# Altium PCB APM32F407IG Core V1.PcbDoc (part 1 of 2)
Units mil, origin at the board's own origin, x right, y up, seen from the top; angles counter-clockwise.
Board outline 2360 x 2950 mil, 4 copper layers (Top Layer, Signal, GND, Bottom Layer); 55 components, 152 nets, 502 pads, 608 vias.
Unrouted connection lines stored in the file: 294.
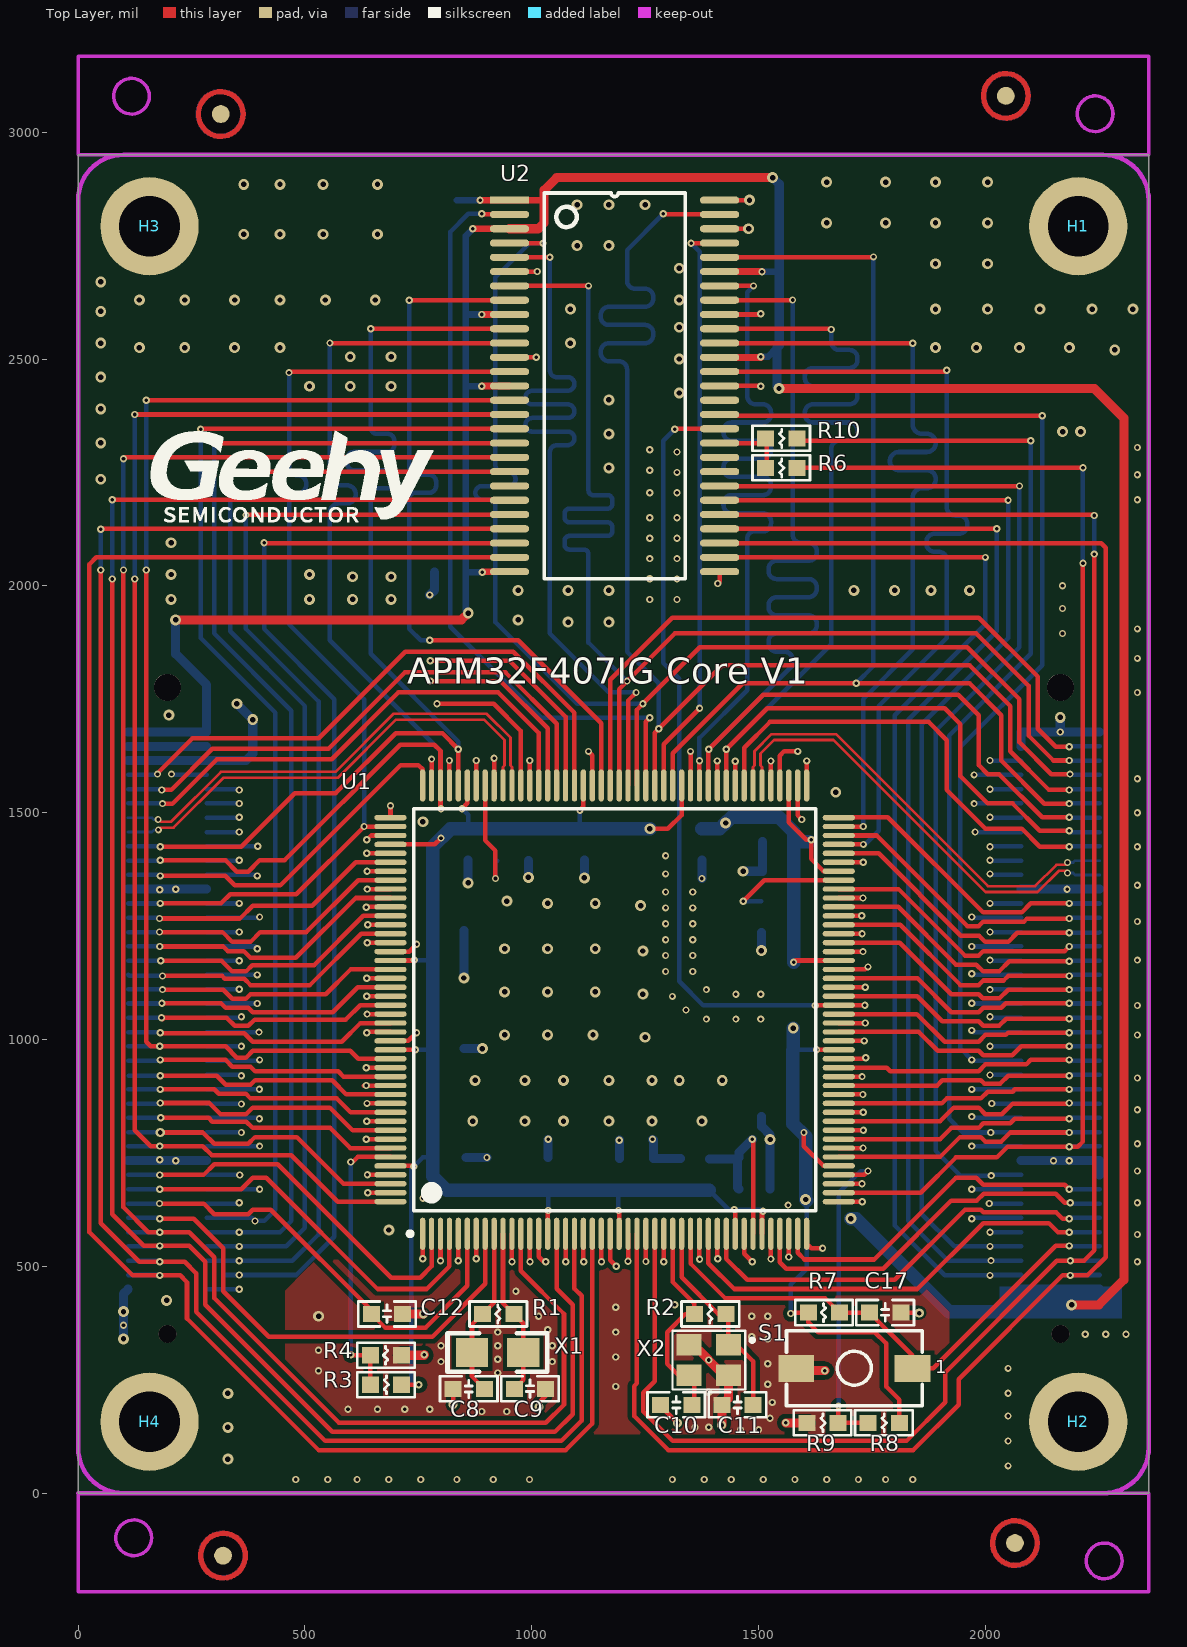
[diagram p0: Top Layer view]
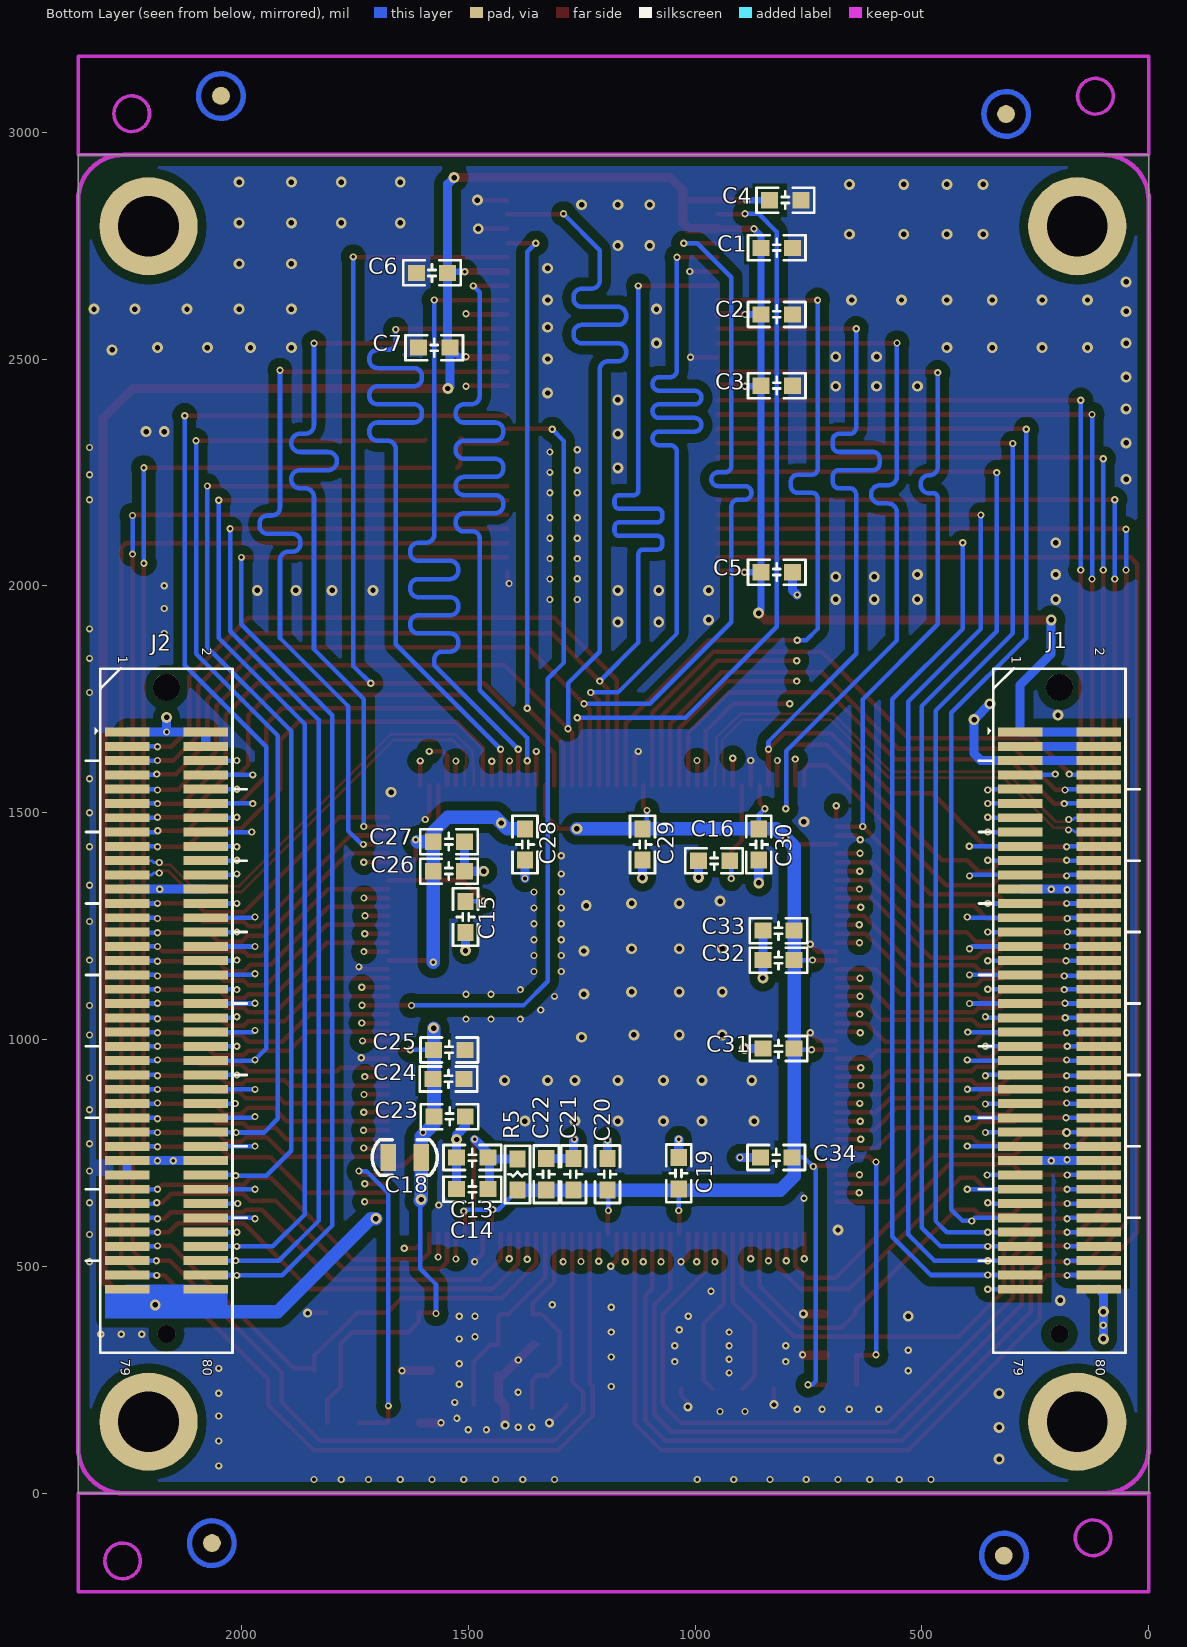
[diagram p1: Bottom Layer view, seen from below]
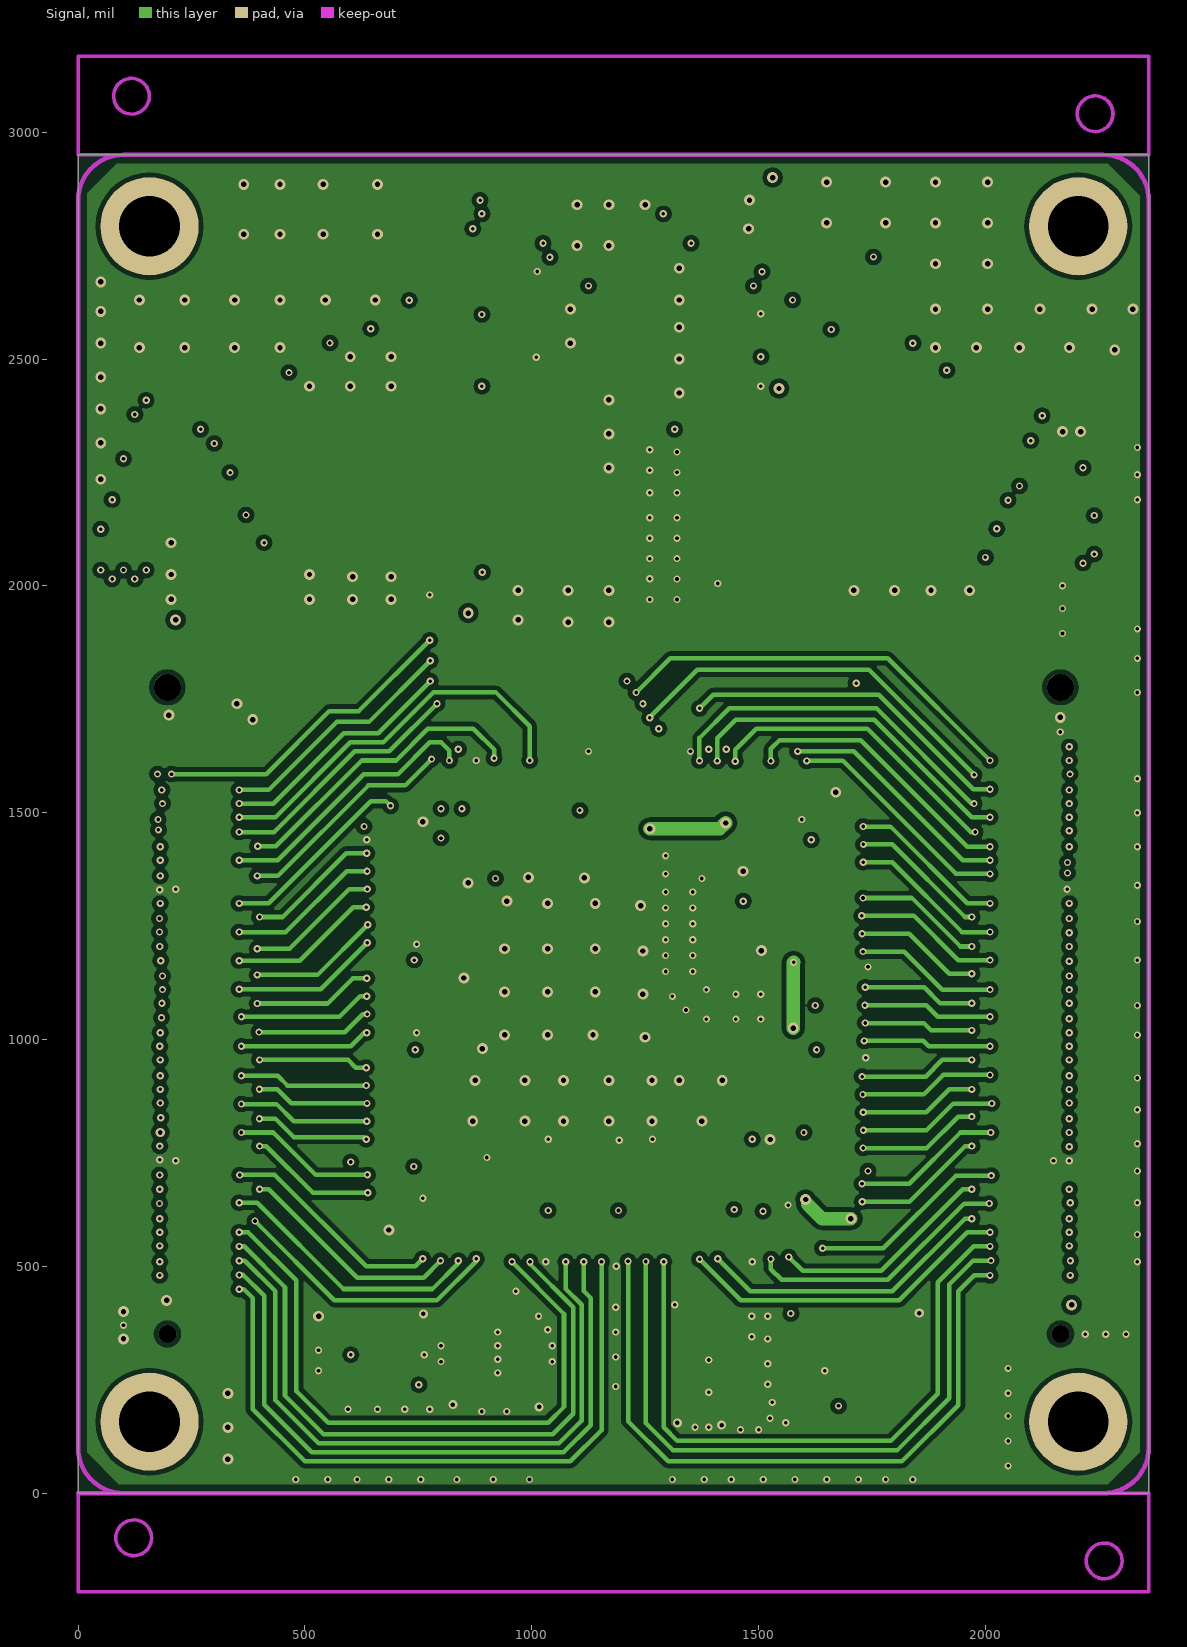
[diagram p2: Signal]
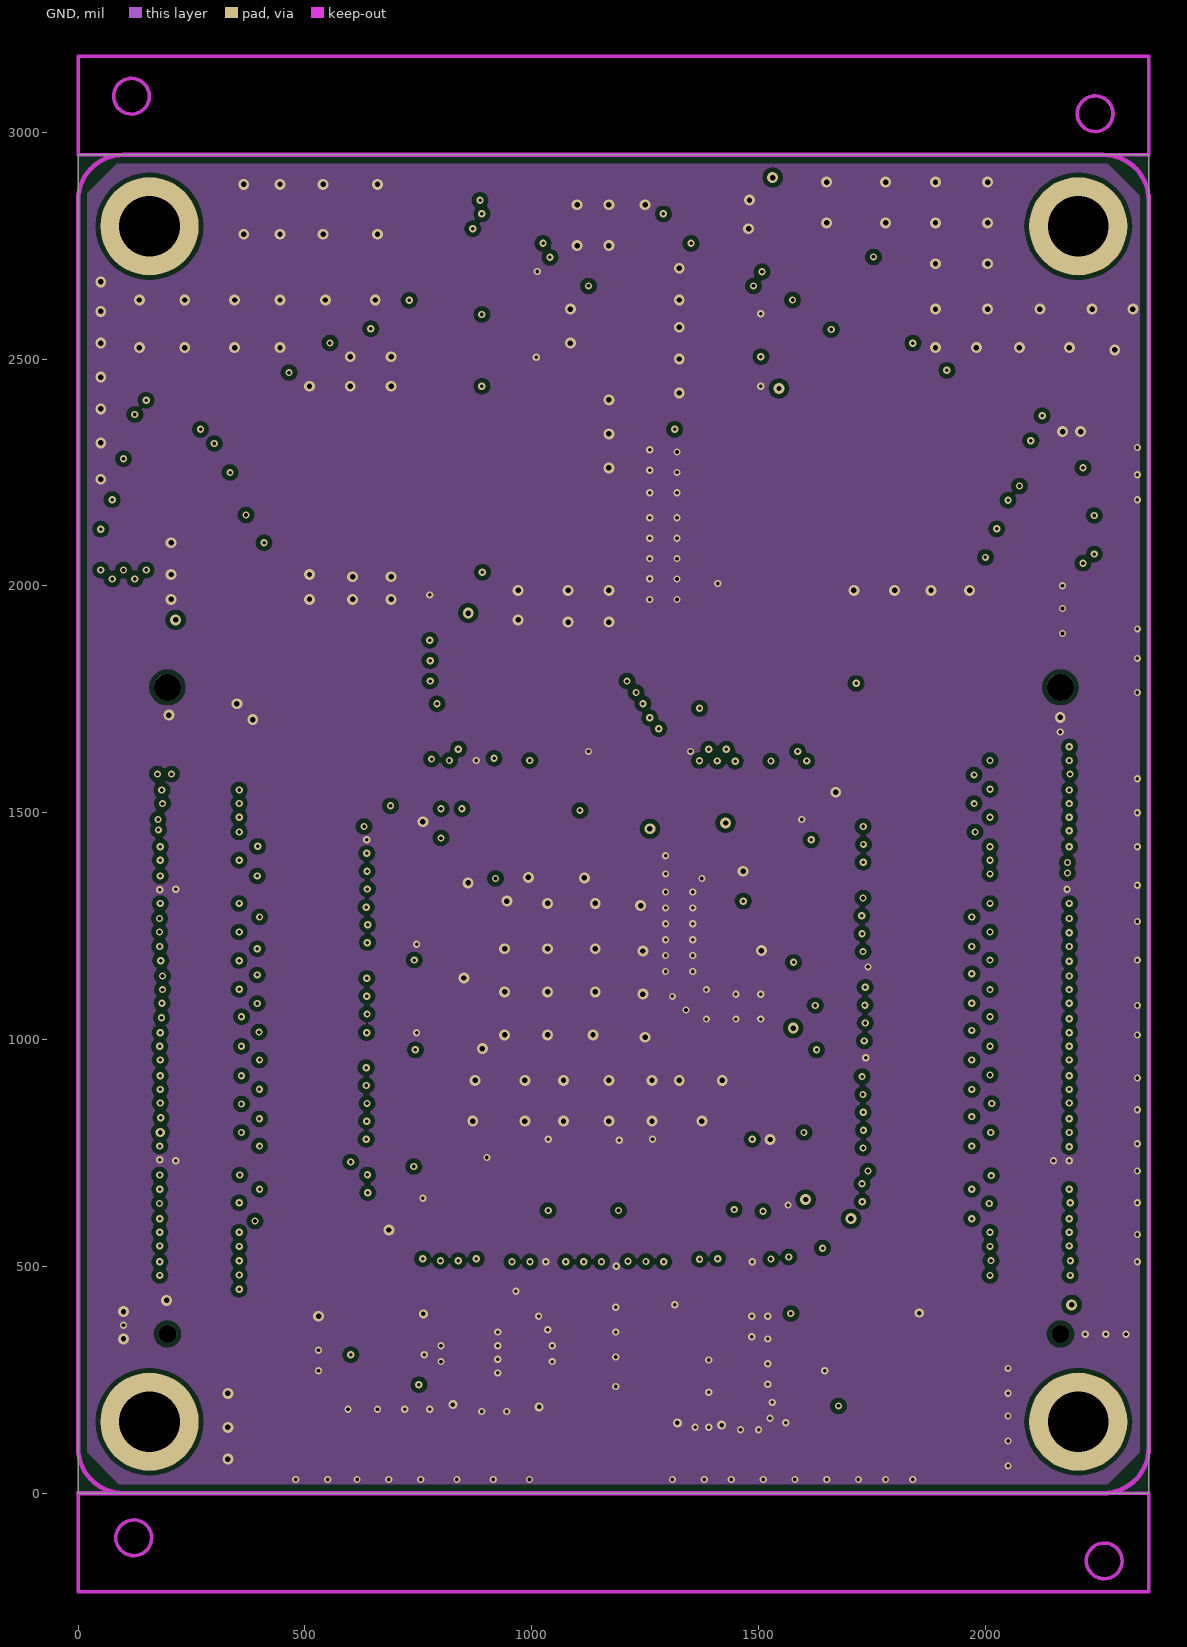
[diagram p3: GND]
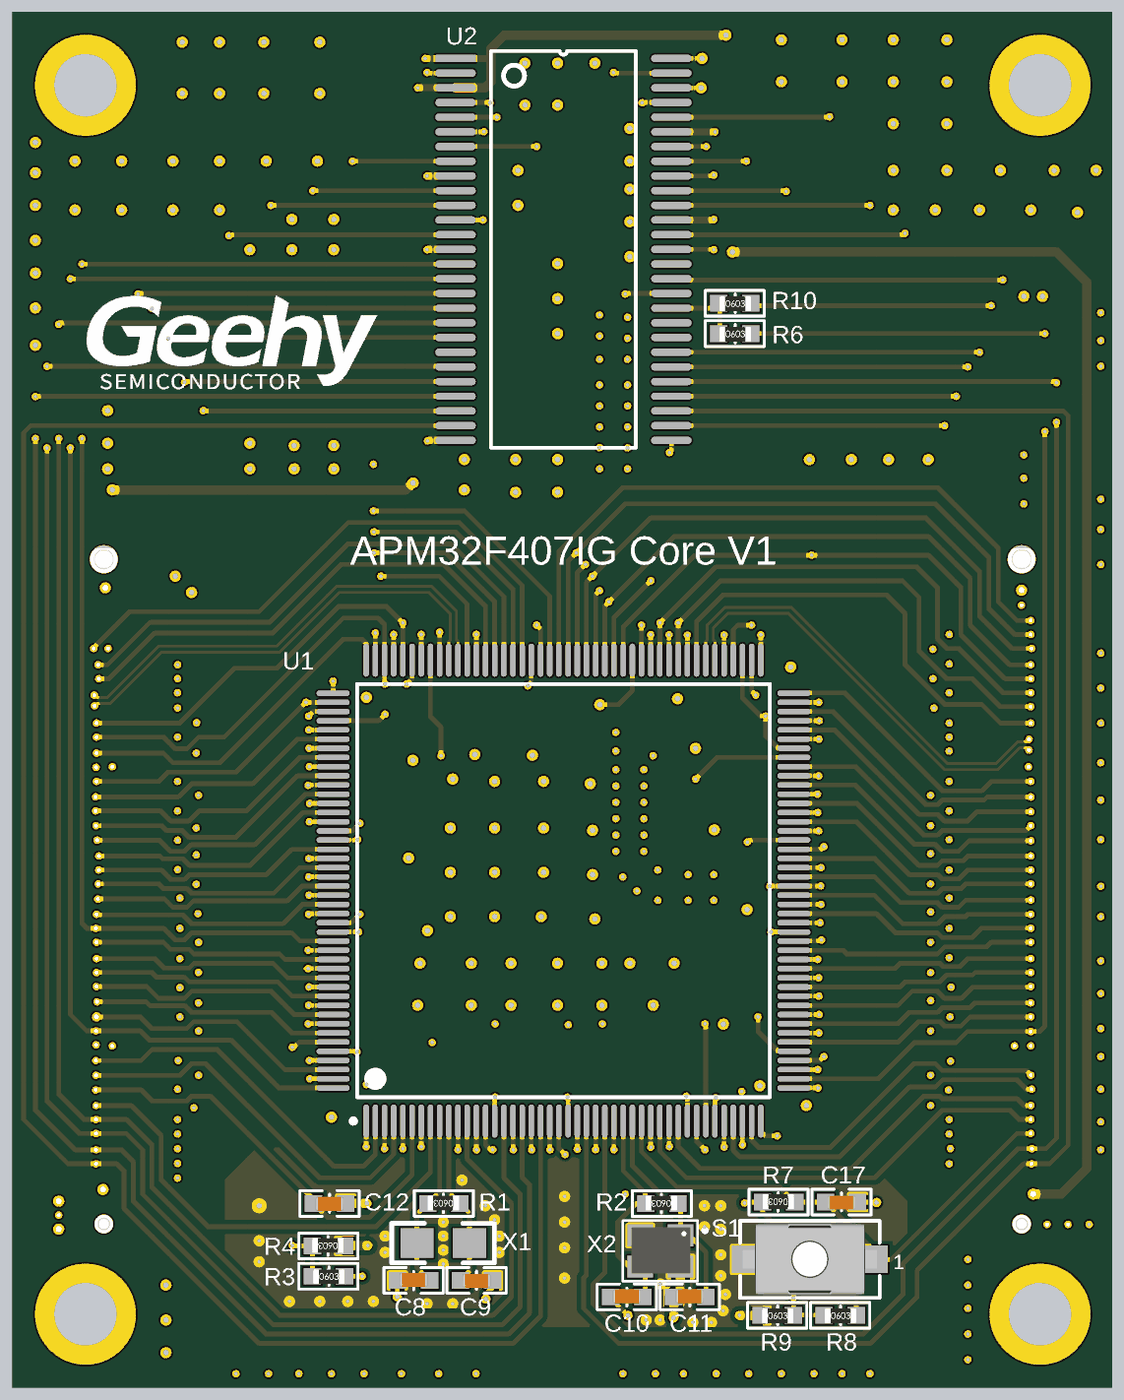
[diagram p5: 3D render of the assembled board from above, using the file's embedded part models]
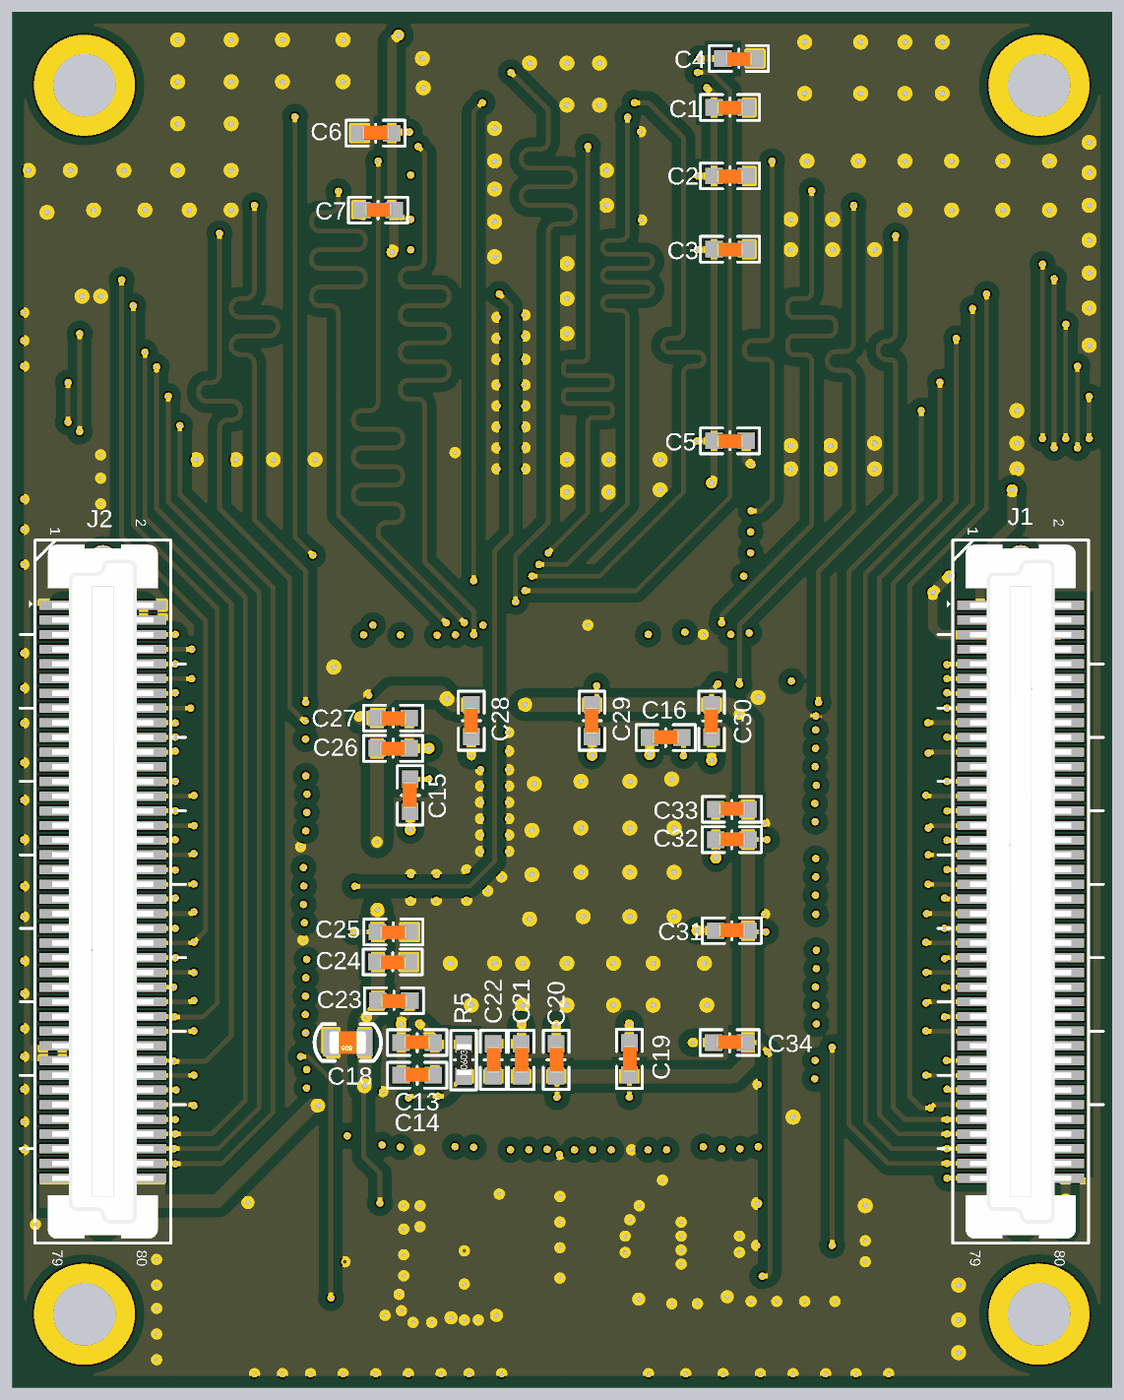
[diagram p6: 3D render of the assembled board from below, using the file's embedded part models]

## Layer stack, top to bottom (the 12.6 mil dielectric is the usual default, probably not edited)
Top Layer: signal copper 1.4
Dielectric: core 12.6, FR-4, Dk 4.8
Signal: signal copper 1.4
Dielectric: prepreg 12.6, FR-4, Dk 4.8
GND: signal copper 1.4
Dielectric: core 12.6, FR-4, Dk 4.8
Bottom Layer: signal copper 1.4

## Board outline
0,2950 0,0 2360,0 2360,2949.97

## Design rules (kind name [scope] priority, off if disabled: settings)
Clearance Clearance_5 [IsRegion vs (OnLayer('Bottom Layer'))] p1: gap=20
Clearance Clearance_4 [InNamedPolygon('B1')] p2: gap=20
Clearance Clearance_3 [InNamedPolygon('B2')] p3: gap=20
Clearance Clearance_2 [InNamedPolygon('B3')] p4: gap=20
Clearance Clearance_1 [IsRegion] p5: gap=10
Clearance [All] p6: gap=6
DiffPairsRouting [All] p1: maxlimit=10 minlimit=1 mostfreqgap=7 maxuncoupledlength=500
HoleSize [All] p1: absolutevalues=TRUE maxlimit=1000 minlimit=1 maxpercent=80.000 minpercent=20.000
MinimumSolderMaskSliver [All] p1: minsoldermaskwidth=0.1
PolygonConnect [All] p1: connectstyle=Direct reliefconductorwidth=10 reliefentries=4 polygonreliefangle="90 Angle" airgapwidth=10
RoutingVias [All] p1: holewidth=10 width=20 viastyle="Through Hole" minholewidth=1 minwidth=1 maxholewidth=28 maxwidth=50
SilkToSilkClearance [All] p1: silktosilkclearance=0.1
SilkToSolderMaskClearance [IsPad] p1: minsilkscreentomaskgap=1 clearancetoexposedcopper=TRUE
SolderMaskExpansion [All] p1: expansion=4
Width [All] p1: maxlimit=100 minlimit=1 preferedwidth=10 minimp=50.000000 maximp=50.000000 favimp=50.000000
23 further rules are at their usual default settings.

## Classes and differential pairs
differential pair class "New Class": NewDifferentialPair1 NewDifferentialPair2 OTG_FS OTG_HS
component class 01_MCU: C8 C9 C10 C11 C12 C13 C14 C15 C16 C17 C18 C19 C20 C21 C22 C23 C24 C25 C26 C27 C28 C29 C30 C31 C32 C33 C34 J3 R1 R2 R3 R4 R5 R7 R8 R9 S1 U1 U4 X1 X2
net class "New Class": PG3_SDR_D0 PG4_SDR_D1 PG5_SDR_D2 PG6_SDR_D3 PG8_SDR_D4 PH13_SDR_D5 PH15_SDR_D6 PI3_SDR_D7
net class "New Class 1": PD10_SDR_D10 PD12_SDR_D11 PD13_SDR_D12 PD14_SDR_D13 PD15_SDR_D14 PG2_SDR_D15 PH8_SDR_D8 PH10_SDR_D9
component class 02_Connect: C1 C2 C3 C4 C5 C6 C7 H1 H2 H3 H4 J1 J2 R6 R10 U2
differential pair NewDifferentialPair2: +PB15_OTG_HS_P -PB14_OTG_HS_N
differential pair NewDifferentialPair1: +PA12_OTG_FS_P -PA11_OTG_FS_N

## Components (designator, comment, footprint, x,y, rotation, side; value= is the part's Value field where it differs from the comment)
C1 "100nF" C0603 820,2745 r180 bottom
C2 "100nF" C0603 820,2598 r180 bottom
C3 "100nF" C0603 820,2441 r180 bottom
C4 "100nF" C0603 801.06,2850 r180 bottom
C5 "100nF" C0603 820,2030 r180 bottom
C6 "100nF" C0603 1580,2690 r0 bottom
C7 "100nF" C0603 1575,2525 r0 bottom
C8 "10pF" C0603 861.06,230 r180 top
C9 "10pF" C0603 996.06,230 r0 top
C10 "20pF" C0603 1318.6,194.75 r180 top
C11 "20pF" C0603 1453.6,194.75 r180 top
C12 "100nF" C0603 681.06,395 r0 top
C13 "1uF" C0603 1491.06,740 r0 bottom
C14 "10nF" C0603 1491.06,670 r0 bottom
C15 "2.2uF" C0603 1506.06,1270 r270 bottom
C16 "2.2uF" C0603 958.06,1394 r0 bottom
C17 "100nF" C0603 1779.06,398 r0 top
C18 "4.7uF" C0805 1640,740 r0 bottom
C19 "100nF" C0603 1036.06,705 r90 bottom
C20 "100nF" C0603 1193.06,703 r90 bottom
C21 "100nF" C0603 1268.06,703 r90 bottom
C22 "100nF" C0603 1328.06,703 r90 bottom
C23 "100nF" C0603 1541.06,830 r180 bottom
C24 "100nF" C0603 1543.61,912.83 r180 bottom
C25 "100nF" C0603 1542,977 r180 bottom
C26 "100nF" C0603 1542.68,1370.83 r180 bottom
C27 "100nF" C0603 1542.68,1435.83 r180 bottom
C28 "100nF" C0603 1375,1430 r270 bottom
C29 "100nF" C0603 1116.06,1430 r270 bottom
C30 "100nF" C0603 859.68,1429.83 r270 bottom
C31 "100nF" C0603 816.06,980 r0 bottom
C32 "100nF" C0603 816.06,1175 r0 bottom
C33 "100nF" C0603 816.06,1240 r0 bottom
C34 "100nF" C0603 821.06,740 r0 bottom
H1 "Value" THC5R5D3R4-M3-PTH#1 2220,2792.52 r0 top
H2 "Value" THC5R5D3R4-M3-PTH#2 2204.72,145 r0 top
H3 "Value" THC5R5D3R4-M3-PTH#3 157.48,2775 r0 top
H4 "Value" THC5R5D3R4-M3-PTH#2 157.48,145 r0 top
J1 "61082-081402LF" B2B2X40R-0R8-SM-Z-H3R7 196.81,1063.57 r270 bottom locked
J2 "61082-081402LF" B2B2X40R-0R8-SM-Z-H3R7 2165.32,1063.56 r270 bottom locked
R1 "NC" R0603 926.06,395 r180 top
R2 "NC" R0603 1393.6,394.75 r180 top
R3 "NC" R0603 678.6,239 r0 top
R4 "10K" R0603 678.6,304 r180 top
R5 "0R" R0603 1391.45,702.17 r90 bottom
R6 "0R" R0603 1550,2260 r0 top
R7 "10K" R0603 1644.06,398 r180 top
R8 "NC" R0603 1776.06,155 r0 top
R9 "10K" R0603 1641.06,155 r0 top
R10 "NC" R0603 1550,2325 r0 top
S1 "434121025816" SW-SMD-6X3R8X2R5-1 1711.06,275 r180 top
U1 "APM32F407IGT6" LQFP-176N 1182.68,1065.83 r90 top locked
U2 "EM638165TS-7IG" TSOP54 951.06,2850 r0 top locked
X1 "32.768KHz" R1206 981.06,310 r180 top
X2 "8MHz" XTAL3225 1390.3,293.21 r180 top

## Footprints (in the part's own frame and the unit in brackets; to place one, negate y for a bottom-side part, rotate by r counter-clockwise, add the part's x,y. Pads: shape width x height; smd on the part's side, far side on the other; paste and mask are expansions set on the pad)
B2B2X40R-0R8-SM-Z-H3R7 [mm]
  rect 0.5x2.5 smd: 1(-15.6,-2.2) 2(-15.6,2.2) 3(-14.8,-2.2) 4(-14.8,2.2) 5(-14,-2.2) 6(-14,2.2) 7(-13.2,-2.2) 8(-13.2,2.2) 9(-12.4,-2.2) 10(-12.4,2.2) 11(-11.6,-2.2) 12(-11.6,2.2) 13(-10.8,-2.2) 14(-10.8,2.2) 15(-10,-2.2) 16(-10,2.2) 17(-9.2,-2.2) 18(-9.2,2.2) 19(-8.4,-2.2) 20(-8.4,2.2) 21(-7.6,-2.2) 22(-7.6,2.2) 23(-6.8,-2.2) 24(-6.8,2.2) 25(-6,-2.2) 26(-6,2.2) 27(-5.2,-2.2) 28(-5.2,2.2) 29(-4.4,-2.2) 30(-4.4,2.2) 31(-3.6,-2.2) 32(-3.6,2.2) 33(-2.8,-2.2) 34(-2.8,2.2) 35(-2,-2.2) 36(-2,2.2) 37(-1.2,-2.2) 38(-1.2,2.2) 39(-0.4,-2.2) 40(-0.4,2.2) 41(0.4,-2.2) 42(0.4,2.2) 43(1.2,-2.2) 44(1.2,2.2) 45(2,-2.2) 46(2,2.2) 47(2.8,-2.2) 48(2.8,2.2) 49(3.6,-2.2) 50(3.6,2.2) 51(4.4,-2.2) 52(4.4,2.2) 53(5.2,-2.2) 54(5.2,2.2) 55(6,-2.2) 56(6,2.2) 57(6.8,-2.2) 58(6.8,2.2) 59(7.6,-2.2) 60(7.6,2.2) 61(8.4,-2.2) 62(8.4,2.2) 63(9.2,-2.2) 64(9.2,2.2) 65(10,-2.2) 66(10,2.2) 67(10.8,-2.2) 68(10.8,2.2) 69(11.6,-2.2) 70(11.6,2.2) 71(12.4,-2.2) 72(12.4,2.2) 73(13.2,-2.2) 74(13.2,2.2) 75(14,-2.2) 76(14,2.2) 77(14.8,-2.2) 78(14.8,2.2) 79(15.6,-2.2) 80(15.6,2.2)
  round 1.5 hole 1.5: 81(-18.1,0)
  round 1 hole 1: 82(18.1,0)
  silkscreen extent -19.16,-4.5 19.15,4.5, body extent -18.9,-3 18.9,3, height 3.7
C0603 [mm]
  rect 0.95x0.9 smd: 1(-0.875,0) 2(0.875,0)
  silkscreen extent -1.61,-0.7 1.61,0.7, body extent -0.76,-0.41 0.76,0.36, height 0.78
C0805 [mm]
  rect 0.86x1.5 smd: 1(-0.92,0) 2(0.92,0)
  silkscreen extent -1.81,-1 1.81,1, body extent -1,-0.62 1,0.63, height 0.78
LQFP-176N [mm] "Thin QFP, 176-Leads, Body 24x24mm, Pitch 0.5mm, IPC Medium Density"
  oval 1.8x0.3 smd: 1(-12.55,10.75) 2(-12.55,10.25) 3(-12.55,9.75) 4(-12.55,9.25) 5(-12.55,8.75) 6(-12.55,8.25) 7(-12.55,7.75) 8(-12.55,7.25) 9(-12.55,6.75) 10(-12.55,6.25) 11(-12.55,5.75) 12(-12.55,5.25) 13(-12.55,4.75) 14(-12.55,4.25) 15(-12.55,3.75) 16(-12.55,3.25) 17(-12.55,2.75) 18(-12.55,2.25) 19(-12.55,1.75) 20(-12.55,1.25) 21(-12.55,0.75) 22(-12.55,0.25) 23(-12.55,-0.25) 24(-12.55,-0.75) 25(-12.55,-1.25) 26(-12.55,-1.75) 27(-12.55,-2.25) 28(-12.55,-2.75) 29(-12.55,-3.25) 30(-12.55,-3.75) 31(-12.55,-4.25) 32(-12.55,-4.75) 33(-12.55,-5.25) 34(-12.55,-5.75) 35(-12.55,-6.25) 36(-12.55,-6.75) 37(-12.55,-7.25) 38(-12.55,-7.75) 39(-12.55,-8.25) 40(-12.55,-8.75) 41(-12.55,-9.25) 42(-12.55,-9.75) 43(-12.55,-10.25) 44(-12.55,-10.75) 89(12.55,-10.75) 90(12.55,-10.25) 91(12.55,-9.75) 92(12.55,-9.25) 93(12.55,-8.75) 94(12.55,-8.25) 95(12.55,-7.75) 96(12.55,-7.25) 97(12.55,-6.75) 98(12.55,-6.25) 99(12.55,-5.75) 100(12.55,-5.25) 101(12.55,-4.75) 102(12.55,-4.25) 103(12.55,-3.75) 104(12.55,-3.25) 105(12.55,-2.75) 106(12.55,-2.25) 107(12.55,-1.75) 108(12.55,-1.25) 109(12.55,-0.75) 110(12.55,-0.25) 111(12.55,0.25) 112(12.55,0.75) 113(12.55,1.25) 114(12.55,1.75) 115(12.55,2.25) 116(12.55,2.75) 117(12.55,3.25) 118(12.55,3.75) 119(12.55,4.25) 120(12.55,4.75) 121(12.55,5.25) 122(12.55,5.75) 123(12.55,6.25) 124(12.55,6.75) 125(12.55,7.25) 126(12.55,7.75) 127(12.55,8.25) 128(12.55,8.75) 129(12.55,9.25) 130(12.55,9.75) 131(12.55,10.25) 132(12.55,10.75)
  oval 0.3x1.8 smd: 45(-10.75,-12.55) 46(-10.25,-12.55) 47(-9.75,-12.55) 48(-9.25,-12.55) 49(-8.75,-12.55) 50(-8.25,-12.55) 51(-7.75,-12.55) 52(-7.25,-12.55) 53(-6.75,-12.55) 54(-6.25,-12.55) 55(-5.75,-12.55) 56(-5.25,-12.55) 57(-4.75,-12.55) 58(-4.25,-12.55) 59(-3.75,-12.55) 60(-3.25,-12.55) 61(-2.75,-12.55) 62(-2.25,-12.55) 63(-1.75,-12.55) 64(-1.25,-12.55) 65(-0.75,-12.55) 66(-0.25,-12.55) 67(0.25,-12.55) 68(0.75,-12.55) 69(1.25,-12.55) 70(1.75,-12.55) 71(2.25,-12.55) 72(2.75,-12.55) 73(3.25,-12.55) 74(3.75,-12.55) 75(4.25,-12.55) 76(4.75,-12.55) 77(5.25,-12.55) 78(5.75,-12.55) 79(6.25,-12.55) 80(6.75,-12.55) 81(7.25,-12.55) 82(7.75,-12.55) 83(8.25,-12.55) 84(8.75,-12.55) 85(9.25,-12.55) 86(9.75,-12.55) 87(10.25,-12.55) 88(10.75,-12.55) 133(10.75,12.55) 134(10.25,12.55) 135(9.75,12.55) 136(9.25,12.55) 137(8.75,12.55) 138(8.25,12.55) 139(7.75,12.55) 140(7.25,12.55) 141(6.75,12.55) 142(6.25,12.55) 143(5.75,12.55) 144(5.25,12.55) 145(4.75,12.55) 146(4.25,12.55) 147(3.75,12.55) 148(3.25,12.55) 149(2.75,12.55) 150(2.25,12.55) 151(1.75,12.55) 152(1.25,12.55) 153(0.75,12.55) 154(0.25,12.55) 155(-0.25,12.55) 156(-0.75,12.55) 157(-1.25,12.55) 158(-1.75,12.55) 159(-2.25,12.55) 160(-2.75,12.55) 161(-3.25,12.55) 162(-3.75,12.55) 163(-4.25,12.55) 164(-4.75,12.55) 165(-5.25,12.55) 166(-5.75,12.55) 167(-6.25,12.55) 168(-6.75,12.55) 169(-7.25,12.55) 170(-7.75,12.55) 171(-8.25,12.55) 172(-8.75,12.55) 173(-9.25,12.55) 174(-9.75,12.55) 175(-10.25,12.55) 176(-10.75,12.55)
  silkscreen extent -12.67,-11.25 11.25,11.57, body extent -12,-12 12,12, height 1.6
R0603 [mm]
  rect 0.95x0.9 smd: 1(-0.875,0) 2(0.875,0)
  silkscreen extent -1.61,-0.7 1.61,0.7, body extent -0.82,-0.43 0.88,0.37, height 0.56
R1206 [mm]
  rect 1.8x1.6 smd: 1(0,0) 2(2.865,0)
  silkscreen extent -1.36,-1.08 4.24,1.08
SW-SMD-6X3R8X2R5-1 [mm]
  rect 2x1.5 smd: 1(-3.25,0) 2(3.25,0)
  silkscreen extent -3.8,-2.1 3.8,2.1, body extent -3.65,-1.96 3.65,1.94, height 2.5
THC5R5D3R4-M3-PTH#1 [mm]
  round 5.5 hole 3.4: 1(-0.388,0)
THC5R5D3R4-M3-PTH#2 [mm]
  round 5.5 hole 3.4: 1(0,0.317)
THC5R5D3R4-M3-PTH#3 [mm]
  round 5.5 hole 3.4: 1(0,0.445)
TSOP54 [mm]
  rect 2.2x0.4 smd: 1(0,0.003)
  oval 2.2x0.4 smd: 2(0,-0.797) 3(0,-1.597) 4(0,-2.397) 5(0,-3.197) 6(0,-3.997) 7(0,-4.797) 8(0,-5.597) 9(0,-6.397) 10(0,-7.197) 11(0,-7.997) 12(0,-8.797) 13(0,-9.597) 14(0,-10.397) 15(0,-11.197) 16(0,-11.997) 17(0,-12.797) 18(0,-13.597) 19(0,-14.397) 20(0,-15.197) 21(0,-15.997) 22(0,-16.797) 23(0,-17.597) 24(0,-18.397) 25(0,-19.197) 26(0,-19.997) 27(0,-20.797) 28(11.76,-20.797) 29(11.76,-19.997) 30(11.76,-19.197) 31(11.76,-18.397) 32(11.76,-17.597) 33(11.76,-16.797) 34(11.76,-15.997) 35(11.76,-15.197) 36(11.76,-14.397) 37(11.76,-13.597) 38(11.76,-12.797) 39(11.76,-11.997) 40(11.76,-11.197) 41(11.76,-10.397) 42(11.76,-9.597) 43(11.76,-8.797) 44(11.76,-7.997) 45(11.76,-7.197) 46(11.76,-6.397) 47(11.76,-5.597) 48(11.76,-4.797) 49(11.76,-3.997) 50(11.76,-3.197) 51(11.76,-2.397) 52(11.76,-1.597) 53(11.76,-0.797) 54(11.76,0.003)
  silkscreen extent 1.93,-21.2 9.82,0.4
XTAL3225 [mm]
  rect 1.4x1.2 smd: 1(-1.1,-0.85) 2(1.1,-0.85) 3(1.1,0.85) 4(-1.1,0.85)
  silkscreen extent -2.48,-1.65 2.04,1.65, body extent -1.63,-1.28 1.57,1.22, height 0.91

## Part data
C1 C2 C3 C4 C5 C6 C7 C12 C17 C19 C20 C21 C22 C23 C24 C25 C26 C27 C28 C29 C30 C31 C32 C33 C34: library part 101CC-00003IA.01, "SMD,电容量100nF,额定电压50V,偏差±10%,材质X7R,0603"
C8 C9: library part 101CC-00365BE.01, "SMD,电容量10pF,额定电压50V,偏差±1pF,材质C0G,0603"
C10 C11: library part 101CC-00471BW.01, "安装方式SMD,电容量20pF,额定电压50V,偏差±5%,材质NPO,0603"
C13: library part 101CC-00005IA.01, "SMD,电容量1uF,额定电压50V,偏差±10%,材质X5R,0603"
C14: library part 101CC-00002IA.01, "SMD,电容量10nF,额定电压50V,偏差±10%,材质X7R,0603"
C15 C16: library part 101CC-00009IA.01, "SMD,电容量2.2uF,额定电压25V,偏差±10%,材质X5R,0603"
C18: library part 101CC-00357OD.01, "SMD,电容量4.7uF,额定电压50V,精度±10%,材质X5R,0805"
H1 H2 H3 H4: library part M3-PTH
J1 J2: library part 101NH-00010CO.01, "SMD,座子,封装脚距0.80mm,180度,引脚数目2x40PIN,塑高/针长3.7mm/无,白色"
R1 R2 R3 R5 R6 R8 R10: library part 101RC-00012IA.01, "SMD,阻值0R,精度±1%,0603,额定功率1/10W"
R4 R7 R9: library part 101RC-00003IA.01, "SMD,阻值10K,精度±1%,0603,额定功率1/10W"
S1: library part 101SA-00035BV.01, "安装方式SMD,封装尺寸6.00x3.80x2.50mm,2PIN,装配角度180度,黑色"
X1: library part XTAL, "Crystal Oscillator"
X2: library part 101XB-00001AN.01, "SMD,材质陶瓷外壳,封装外壳3225,精度±10ppm,震荡频率8MHz"

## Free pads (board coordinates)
  round 39.37 smd: 1(314.48,3039.87) 1(319.48,-137.8) 1(2045,3080) 1(2065,-110)
  round 39.37 smd far side: 6(314.48,3039.87) 6(319.48,-137.8) 6(2045,3080) 6(2065,-110)

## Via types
v1: diameter 16, hole 8, Top Layer to Bottom Layer, 452 vias
v2: diameter 24, hole 12, Top Layer to Bottom Layer, 149 vias
v3: diameter 20, hole 10, Top Layer to Bottom Layer, 7 vias

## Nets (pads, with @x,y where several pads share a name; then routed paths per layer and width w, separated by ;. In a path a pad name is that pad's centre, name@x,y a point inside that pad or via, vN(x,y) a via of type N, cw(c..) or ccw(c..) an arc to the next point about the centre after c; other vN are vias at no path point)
+3V3: C1.1 C2.1 C3.1 C4.1 C5.1 C6.1 C7.1 C18.1 C19.1 C20.1 C21.1 C22.1 C23.1 C24.1 C25.1 C26.1 C27.1 C28.1 C29.1 C30.1 C31.1 C32.1 C33.1 C34.1 J1.1 J1.2 J2.79 J2.80 R3.2 R5.1 R7.2 R8.2 U1.15 U1.23 U1.36 U1.39 U1.49 U1.62 U1.72 U1.82 U1.91 U1.103 U1.114 U1.127 U1.136 U1.149 U1.159 U1.172 U2.1 U2.3 U2.9 U2.14 U2.27 U2.43 U2.49 | length 13735.3
  Top Layer w10: U1.172@688.58,721.34 738.43,721.34 v1(739.76,720) ; U1.159@688.58,977.24 v1(743.31,977.24) ; U1.149@688.58,1174.09 740.16,1174.09 v1(741.06,1175) ; U1.136@688.58,1430 786.06,1430 v1(800,1443.94) ; R3.2@713.05,239 v1(751.06,239) ; v1(846.06,1508.74) 857.87,1520.55 U1.127@857.87,1559.92 ; U1.15@1035.04,571.73 1035.04,621.89 v1(1036.06,622.91) ; v1(1106.06,1505) 1113.78,1512.72 U1.114@1113.78,1559.92 ; v1(1191.06,622.91) 1192.52,621.46 U1.23@1192.52,571.73 ; v2@1260,1464.45 1300,1464.45 1330.32,1494.76 U1.103@1330.32,1559.92 ; v1(1446.06,625) 1448.43,622.64 U1.36@1448.43,571.73 ; U1.39@1507.48,571.73 1507.48,621.5 v1(1509.65,621.5) ; U1.91@1566.54,1559.92 1566.54,1478.46 1605,1440 v1(1616.06,1440) 1616.06,1397.9 1643.02,1370.95 U1.82@1676.77,1370.95 ; v1(1571.06,396) 1573.06,398 R7.2@1609.61,398 1609.61,376.45 1631.06,355 1756.06,355 1781.06,330 1781.06,235 1810.51,205.55 R8.2@1810.51,155 ; v1(1577.13,1170) 1581.22,1174.09 U1.72@1676.77,1174.09 ; v1(1599.84,795) 1599.84,764.52 1643.02,721.34 U1.49@1676.77,721.34 ; v1(1627.83,977.24) U1.62@1676.77,977.24
  Top Layer w15: v1(870,2787.11) U2.3@951.05,2787.11 ; v1(886.06,2850) 886.17,2850.1 U2.1@951.05,2850.1 1027.13,2850.1 1027.24,2850 ; v1(890,2440) 890.65,2440.65 U2.14@951.05,2440.65 ; v1@890.13,2598.13 U2.9@951.05,2598.13 ; v1@892.2,2031.2 U2.27@951.05,2031.2 ; U2.43@1414.05,2503.65 v1@1505,2503.65 ; U2.49@1414.05,2692.62 1507.62,2692.62 v1(1507.62,2692.38)
  Top Layer w20: v2(215,1925) 845,1925 v2(860,1940) ; U2.3@951.05,2787.11 1014.35,2787.11 1027.24,2800 1027.24,2850 1027.24,2872.24 1055,2900 v2(1531.06,2900) ; v2(1545,2435) 2240,2435 2305,2370 2305,470 2250,415 v2(2190,415)
  Signal w30: v2(1260.55,1464.45) 1414.45,1464.45 v2(1427.22,1477.22) ; v2(1576.45,1025) 1576.45,1169.32 v1(1577.13,1170) ; v2@1608.56,636.44 1640,605 v2(1703.56,605)
  Bottom Layer w10: v1(741.06,1175) C32.1@781.61,1175 ; v1(743.31,977.24) 778.86,977.24 C31.1@781.61,980 ; v1(751.06,239) 742.06,239 734.5,246.56 734.5,714.74 v1(739.76,720) 759.76,740 781.61,740 C34.1@786.61,740 ; v1(846.06,1508.74) 859.68,1495.13 C30.1@859.68,1464.28 ; v1(1036.06,622.91) 1036.06,667.72 C19.1@1036.06,670.55 ; v1(1106.06,1505) 1106.06,1474.45 C29.1@1116.06,1464.45 ; v1(1191.06,622.91) 1191.06,666.55 1192.24,667.72 C20.1@1193.06,668.55 ; R5.1@1391.45,667.72 1434.17,625 v1(1446.06,625) 1506.14,625 v1(1509.65,621.5) ; v1(1571.06,396) 1571.06,460 1606.06,495 v2@1606.06,645 ; C25.1@1578.54,977.24 v1(1627.83,977.24)
  Bottom Layer w15: C4.1@835.51,2850 v1(886.06,2850) ; v2(860,1940) 854.45,1945.55 C5.1@854.45,2030 ; v1(870,2787.11) 854.45,2771.56 C1.1@854.45,2745 C2.1@854.45,2598 ; v1(890,2440) 855.45,2440 C3.1@854.45,2441 ; v1(890,2598) C2.1@854.45,2598 ; v1(891,2030) C5.1@854.45,2030 ; v1(1505,2505) 1520.55,2505 C7.1@1540.55,2525 ; v1(1507.62,2692.38) 1543.17,2692.38 C6.1@1545.55,2690 ; C5.1@854.45,2030 C3.1@854.45,2441 ; C3.1@854.45,2441 C2.1@854.45,2598
  Bottom Layer w20: J1.2@110.2,1677.74 J1.1@283.43,1677.74 283.43,1781.57 215,1850 v2(215,1925) ; v2(1531.06,2900) 1545.55,2885.51 C6.1@1545.55,2690 1545.55,2530 C7.1@1540.55,2525 1540.55,2439.45 v2(1545,2435) ; J2.80@2078.7,449.39 J2.79@2251.93,449.39
  Bottom Layer w30: v2(1260.55,1464.45) C29.1@1116.06,1464.45 859.85,1464.45 C30.1@859.68,1464.28 820.72,1464.28 781.61,1425.17 C33.1@781.61,1240 C32.1@781.61,1175 C31.1@781.61,980 781.61,740 781.61,698.39 812.28,667.72 1036.06,667.72 1192.24,667.72 R5.1@1391.45,667.72 ; C28.1@1375,1464.45 1414.45,1464.45 v2(1427.22,1477.22) 1440,1490 1545,1490 1577.13,1457.87 C27.1@1577.13,1435.83 ; C25.1@1575.51,975.83 C23.1@1575.51,830 1575.51,814.49 1603.78,786.22 C18.1@1603.78,740 v2(1603.78,647.28) v2@1606.06,645 ; C25.1@1576.45,977 v2(1576.45,1025) ; v1(1577.13,1170) C26.1@1577.13,1370.83 C27.1@1577.13,1435.83 ; v1@1611.89,1435.83 C27.1@1577.13,1435.83 ; v2(1703.56,605) 1715,605 1920,400 2136.06,400 2171.06,435
+5V: J1.3 J1.4 | length 173.2
  Bottom Layer w20: J1.4@110.2,1646.24 J1.3@283.43,1646.24
BOOT0: J1.52 U1.166 | length 599.5
  Top Layer w10: v1(181.06,890) 300,890 310,880 370,880 380,870 570,870 600.55,839.45 U1.166@688.58,839.45
  Bottom Layer w10: J1.52@110.2,890.34 110.53,890 v1(181.06,890)
BYPASS_RGE: R8.1 R9.2 U1.48 | length 724.3
  Top Layer w10: v1(1676.06,192.32) 1676.06,155.55 1741.06,155.55 R8.1@1741.61,155 ; U1.48@1676.77,701.65 1732.72,701.65 v1(1741.06,710)
  Bottom Layer w10: v1(1676.06,192.32) 1676.77,193.03 1676.77,661.77 1725,710 v1(1741.06,710)
GND: C1.2 C2.2 C3.2 C4.2 C5.2 C6.2 C7.2 C8.2 C9.2 C10.2 C11.2 C12.2 C13.2 C14.2 C15.2 C16.2 C17.2 C18.2 C19.2 C20.2 C21.2 C22.2 C23.2 C24.2 C25.2 C26.2 C27.2 C28.2 C29.2 C30.2 C31.2 C32.2 C33.2 C34.2 J1.5 J1.6 J1.23 J1.24 J1.61 J1.62 J1.80 J2.1 J2.2 J2.4 J2.23 J2.24 J2.61 J2.62 J2.63 R4.1 R9.1 S1.2 U1.14 U1.22 U1.37 U1.61 U1.71 U1.90 U1.102 U1.113 U1.126 U1.135 U1.148 U1.158 U2.6 U2.12 U2.28 U2.41 U2.46 U2.52 U2.54 X2.2 X2.4 | length 4282.2
  Top Layer w10: v1(636.06,1440) 645.75,1449.69 U1.135@688.58,1449.69 ; U1.158@688.58,996.93 727.99,996.93 v1(746.06,1015) ; U1.148@688.58,1193.78 729.84,1193.78 v1(746.06,1210) ; v3(826.06,195) 826.61,195.55 C8.2@826.61,230 ; U1.126@877.56,1559.92 v1(877.56,1615) ; U2.12@951.05,2503.65 v1(1010,2503.65) ; U2.6@951.05,2692.62 1011.62,2692.62 v1(1012,2693) ; U1.14@1015.35,571.73 1015.35,520.71 1026.06,510 v1(1031.06,510) ; v3(1016.06,190) 1016.06,200 1030.51,214.45 C9.2@1030.51,230 ; v1(1125,1635) 1133.46,1626.54 U1.113@1133.46,1559.92 ; U1.22@1172.83,571.73 1172.83,513.23 v1(1186.06,500) ; C10.2@1284.16,194.75 1284.16,191.91 v3(1321.06,155) ; X2.2@1346.99,326.68 X2.2@1356.67,326.68 ; U1.102@1350,1559.92 v1(1350,1635) ; v1(1410,2005) 1414.05,2009.05 U2.28@1414.05,2031.2 ; U2.41@1414.05,2440.65 v1@1505,2440.65 ; U2.46@1414.05,2598.13 v1@1505,2598.13 ; U2.52@1414.05,2787.11 v2(1477.89,2787.11) ; U2.54@1414.05,2850.1 v2(1479.9,2850.1) ; X2.4@1423.6,259.75 X2.4@1433.6,259.75 ; U1.37@1468.11,571.73 1468.11,527.95 v1(1486.06,510) ; U1.90@1586.22,1559.92 1586.22,1493.78 v1(1595,1485) ; U1.61@1676.77,957.56 1733.62,957.56 v1(1736.06,960) ; U1.71@1676.77,1154.41 1735.47,1154.41 v1(1741.06,1160) ; C17.2@1813.51,398 1854.06,398 v3(1854.06,397)
  Top Layer w20: R4.1@713.05,304 762.01,304 v1(763.01,305) ; C12.2@715.51,395 v3(761.06,395) ; X2.2@1356.67,326.68 X2.4@1423.6,259.75 ; v3(1418.6,149.75) 1419.16,150.3 C11.2@1419.16,194.75 1433.6,209.2 X2.4@1433.6,259.75 ; v1(1560,155) R9.1@1606.61,155 ; S1.2@1583.11,270 v1(1646.06,270)
  Bottom Layer w20: v2(100,340) v2(100,400) 100,439.19 J1.80@110.2,449.39 ; J1.62@110.2,732.86 J1.61@283.43,732.86 ; J1.24@110.2,1331.28 J1.23@283.43,1331.28 ; J1.6@110.2,1614.75 J1.5@283.43,1614.75 369.75,1614.75 385,1630 v2(385,1705) v2(350,1740) ; v1(775,1980) 785.55,1990.55 C5.2@785.55,2030 ; C31.2@850.51,980 v2(891.06,980) ; v2(850.51,1135.51) C32.2@850.51,1175 C33.2@850.51,1240 ; C34.2@855.51,740 v1(901.06,740) ; v2(859.68,1345.32) C30.2@859.68,1395.38 ; v2(992.51,1357.49) C16.2@992.51,1394 ; C19.2@1036.06,739.45 v1(1036.06,780) ; v2(1116.06,1356.06) C29.2@1116.06,1395.55 ; C20.2@1193.06,737.45 v1(1193.06,778) ; v1(1266.06,780) 1268.06,778 C21.2@1268.06,737.45 C22.2@1328.06,737.45 ; v1(1375,1355) C28.2@1375,1395.55 ; v2(1465.83,1370.83) C26.2@1508.23,1370.83 C27.2@1508.23,1435.83 ; v2(1506.06,1196.06) C15.2@1506.06,1235.55 ; C23.2@1506.61,830 1506.61,808.39 1525.51,789.49 v2(1525.51,779.49) C13.2@1525.51,740 C14.2@1525.51,670 ; J2.62@2078.7,732.86 J2.61@2251.93,732.86 J2.63@2251.93,701.36 ; J2.24@2078.7,1331.28 J2.23@2251.93,1331.28 ; J2.4@2078.7,1646.24 J2.2@2078.7,1677.74 v1(2165,1677.74) ; v2(2165,1710) v1(2165,1677.74) ; J2.1@2251.93,1677.74 v1(2165,1677.74)
  other v1: 480,30 550,30 615,30 685,30 755,30 835,30 915,30 995,30 1310,30 1380,30 1440,30 1510,30 1580,30 1650,30 1720,30 1780,30 1840,30 2050,60 2050,115 1460,140 1500,140 1360,145 1390,145 1525,165 2050,170 890,180 945,180 595,185 660,185 720,185 775,185 1530,200 2050,220 1390.16,222.31 1185,235 1520,240 925,265 530,270 2050,275 1520,285 800,290 1045,290 1390,293.35 925,295 1185,300 530,315 800,325 925,325 1045,325 1520,340 1485,345 2220,350 2265,350 2310,350 925,355 1185,355 1035,360 100,370 1015,390 1485,390 1520,390 1185,410 1315,415 965,445 2335,510 2335,570 1565,635 2335,640 760,650 2335,710 215,732.86 2150,732.86 2185,732.86 180,735 2335,770 2335,845 2335,915 2335,1010 1385,1045 1450,1045 1505,1045 1340,1065 2335,1075 1310,1095 1450,1100 1505,1100 1385,1110 1295,1150 1355,1150 2335,1175 1295,1185 1355,1185 1295,1220 1355,1220 1295,1255 1355,1255 2335,1260 1295,1290 1355,1290 1295,1325 1355,1325 180,1330 215,1331.28 2180,1331.28 2335,1340 1295,1365 1295,1405 2335,1425 2335,1500 2335,1575 2335,1765 2335,1840 2170,1895 2335,1905 2170,1950 1260,1970 1320,1970 2170,2000 1320,2015 1260,2015.46 1260,2060 1320,2060 1260,2105 1320,2105 1260,2150 1320,2150 2335,2190 1260,2205 1320,2205 2335,2245 1320,2250 1260,2255 1320,2295 1260,2300 2335,2305 1505,2440 1505,2600
  other v2: 330,75 330,145 330,220 530,390 195,425 685,580 870,820 985,820 1070,820 1170,820 1265,820 1375,820 875,910 985,910 1070,910 1170,910 1265,910 1325,910 1420,910 1250,1005 940,1010 1035,1010 1135,1010 1245,1100 940,1105 1035,1105 1140,1105 1245,1195 940,1200 1035,1200 1140,1200 1240,1295 1035,1300 1140,1300 945,1305 760,1480 1670,1545 200,1715 1080,1920 1170,1920 970,1925 205,1970 510,1970 605,1970 690,1970 970,1990 1080,1990 1170,1990 1710,1990 1800,1990 1880,1990 1965,1990 605,2020 690,2020 205,2025 510,2025 205,2095 50,2235 1170,2260 50,2315 1170,2335 2170,2340 2210,2340 50,2390 1170,2410 1325,2425 510,2440 600,2440 690,2440 50,2460 1325,2500 600,2505 690,2505 2285,2520 135,2525 235,2525 345,2525 445,2525 1890,2525 1980,2525 2075,2525 2185,2525 50,2535 1085,2535 1325,2570 50,2605 1085,2610 1890,2610 2005,2610 2120,2610 2235,2610 2325,2610 135,2630 235,2630 345,2630 445,2630 545,2630 655,2630 1325,2630 50,2670 1325,2700 1890,2710 2005,2710 1100,2750 1170,2750 365,2775 445,2775 540,2775 660,2775 1650,2800 1780,2800 1890,2800 2005,2800 1100,2840 1170,2840 1250,2840 365,2885 445,2885 540,2885 660,2885 1650,2890 1780,2890 1890,2890 2005,2890
NetC13_1: C13.1 C14.1 R5.2 U1.38 | length 391
  Top Layer w10: v1(1486.06,780) 1487.8,778.27 U1.38@1487.8,571.73
  Bottom Layer w20: R5.2@1391.45,736.62 1453.24,736.62 1453.24,673.38 C14.1@1456.61,670 ; C13.1@1456.61,740 1456.61,750.55 v1(1486.06,780)
NetC15_1: C15.1 U1.81 | length 270.1
  Top Layer w10: v1(1466.06,1305) 1512.32,1351.26 U1.81@1676.77,1351.26
  Bottom Layer w10: v1(1466.06,1305) 1466.61,1304.45 C15.1@1506.06,1304.45
NetC16_1: C16.1 U1.125 | length 254.8
  Top Layer w10: U1.125@897.24,1559.92 897.24,1438.74 920,1415.98 v1(920,1355)
  Bottom Layer w10: v1(920,1355) 920,1390.39 C16.1@923.61,1394
PA0_CAMRE_PW: J2.68 U1.40 | length 709
  Top Layer w10: v1(1527.17,516.1) U1.40@1527.17,571.73
  Signal w10: v1(1527.17,516.1) 1527.17,493.9 1551.06,470 1785,470 1953.37,638.37 v1(2008.37,638.37)
  Bottom Layer w10: v1(2008.37,638.37) J2.68@2078.7,638.37
PA1_RMII_REF_CLK: J2.67 U1.41 | length 850.8
  Top Layer w10: U1.41@1546.85,571.73 1546.85,509.21 1561.06,495 1775,495 1925,645 1981,645 1996,660 2155,660 2175,640 v1(2186.74,640)
  Bottom Layer w10: v1(2186.74,640) 2188.37,638.37 J2.67@2251.93,638.37
PA2_ETH_MDIO: J2.66 U1.42 | length 650.7
  Top Layer w10: v1(1566.54,520.47) U1.42@1566.54,571.73
  Signal w10: v1(1566.54,520.47) 1597.01,490 1770,490 1950,670 v1(1970,670)
  Bottom Layer w10: v1(1970,670) 1970.14,669.86 J2.66@2078.7,669.86
PA3_SDR_CKE: J2.58 R10.2 U1.47 | length 2631.2
  Top Layer w10: R10.2@1594.28,2322.32 1596.6,2320 v1(2100,2320) ; U1.47@1676.77,681.97 v1(1728.03,681.97)
  Signal w10: v1(1728.03,681.97) 1831.97,681.97 1945,795 v1(2011.7,795)
  Bottom Layer w10: J2.58@2078.7,795.85 2010.85,795.85 v1(2011.7,795) 1950,795 1920,825 1920,1670 2100,1850 v1(2100,2320)
PA4_DCMI_HS: J2.57 U1.50 | length 606.2
  Top Layer w10: U1.50@1676.77,741.02 1900,741.02 1943.98,785 1990,785 2000,775 2035,775 2055,795 v1(2185,795)
  Bottom Layer w10: v1(2185,795) 2185.85,795.85 J2.57@2251.93,795.85
PA5_KEY4: J2.56 U1.51 | length 431.7
  Top Layer w10: U1.51@1676.77,760.71 v1(1730.35,760.71)
  Signal w10: v1(1730.35,760.71) 1870.71,760.71 1940,830 v1(1970,830)
  Bottom Layer w10: v1(1970,830) 1972.66,827.34 J2.56@2078.7,827.34
PA6_DCMI_PIXCK: J2.55 U1.52 | length 594.6
  Top Layer w10: U1.52@1676.77,780.39 1900,780.39 1924.61,805 1985,805 1995,815 2055,815 2065,825 v1(2185,825)
  Bottom Layer w10: v1(2185,825) 2187.34,827.34 J2.55@2251.93,827.34
PA7_RMII_CRS_DV: J2.54 U1.53 | length 426.3
  Top Layer w10: U1.53@1676.77,800.08 v1(1730.98,800.08)
  Signal w10: v1(1730.98,800.08) 1870.08,800.08 1928.84,858.84 v1(2013.84,858.84)
  Bottom Layer w10: v1(2013.84,858.84) J2.54@2078.7,858.84
PA8_CAMER_XCLK: J1.12 U1.119 | length 1159.5
  Top Layer w10: v1(186.06,1520) 208,1520 306,1618 559.06,1618 706.06,1765 926.06,1765 1015.35,1675.71 U1.119@1015.35,1559.92
  Signal w10: v1@185.81,1520.26 v1(186.06,1520)
  Bottom Layer w10: J1.12@110.2,1520.26 v1@185.81,1520.26
PA9_USART1_TX: J1.13 U1.120 | length 988
  Top Layer w10: U1.120@995.67,1559.92 v1(995.67,1615)
  Signal w10: v1(355,1490) 435,1490 600,1655 673.06,1655 783.06,1765 921.06,1765 995.67,1690.39 v1(995.67,1615)
  Bottom Layer w10: J1.13@283.43,1488.76 353.76,1488.76 v1(355,1490)
PA10_USART1_RX: J1.15 U1.121 | length 954.6
  Top Layer w10: v1(791.06,1740) 916.06,1740 975.98,1680.08 U1.121@975.98,1559.92
  Signal w10: v1(355,1457.27) 432.27,1457.27 610,1635 686.06,1635 v1(791.06,1740)
  Bottom Layer w10: J1.15@283.43,1457.27 v1(355,1457.27)
PA11_OTG_FS_N: J1.14 U1.122 | length 1073.6
  Top Layer w6: v1(176.25,1485) 181.25,1480 205,1480 315,1590 567.68,1590 695.68,1718 900.34,1718 952.96,1665.38 952.96,1604.17 956.3,1600.83 U1.122@956.3,1559.92
  Bottom Layer w6: J1.14@110.2,1488.76 162.68,1488.76 166.44,1485 v1(176.25,1485)
PA12_OTG_FS_P: J1.16 U1.123 | length 1052.5
  Top Layer w6: v1(177,1462) 182,1467 210.38,1467 320.38,1577 573.06,1577 701.06,1705 894.96,1705 939.96,1660 939.96,1604.17 936.61,1600.83 U1.123@936.61,1559.92
  Bottom Layer w6: J1.16@110.2,1457.27 162.68,1457.27 167.41,1462 v1(177,1462)
PA13_SWDIO: J1.17 U1.124 | length 840.2
  Top Layer w10: U1.124@916.93,1559.92 v1(916.93,1620)
  Signal w10: v1(395.77,1425.77) 435.77,1425.77 625,1615 701.06,1615 771.06,1685 871.06,1685 916.93,1639.13 v1(916.93,1620)
  Bottom Layer w10: J1.17@283.43,1425.77 v1(395.77,1425.77) v1@395,1425
PA14_SWCLK: J1.27 U1.137 | length 464
  Top Layer w10: v1(636.38,1410.32) U1.137@688.58,1410.32
  Signal w10: v1(400,1270) 451.06,1270 591.38,1410.32 v1(636.38,1410.32)
  Bottom Layer w10: J1.27@283.43,1268.29 398.29,1268.29 v1(400,1270)
PA15_TDI: J1.28 U1.138 | length 631.3
  Top Layer w10: v1(179.35,1266.71) 356.71,1266.71 385,1295 516.06,1295 611.69,1390.63 U1.138@688.58,1390.63
  Signal w10: v1(179.35,1266.71) v1@179.35,1268.29
  Bottom Layer w10: J1.28@110.2,1268.29 v1@179.35,1268.29
PB0_KEY1: J2.51 U1.56 | length 588.1
  Top Layer w10: U1.56@1676.77,859.13 1904.13,859.13 1915,870 1990,870 2005,885 2060,885 2065,890 v1(2185,890)
  Bottom Layer w10: v1(2185,890) 2185.34,890.34 J2.51@2251.93,890.34
PB1_KEY2: J2.50 U1.57 | length 419.7
  Top Layer w10: U1.57@1676.77,878.82 v1(1729.88,878.82)
  Signal w10: v1(1729.88,878.82) 1863.82,878.82 1906.83,921.83 v1(2010,921.83)
  Bottom Layer w10: v1(2010,921.83) J2.50@2078.7,921.83
PB2_BOOT1: J2.49 U1.58 | length 590.8
  Top Layer w10: U1.58@1676.77,898.5 1893.5,898.5 1905,910 1990,910 1997.17,902.83 2032.83,902.83 2050,920 v1(2185,920)
  Bottom Layer w10: v1(2185,920) 2186.83,921.83 J2.49@2251.93,921.83
PB3_SPI_SCK: J1.47 U1.161 | length 412.9
  Top Layer w10: v1(635,937.87) U1.161@688.58,937.87
  Signal w10: v1(400,955) 595,955 612.13,937.87 v1(635,937.87)
  Bottom Layer w10: J1.47@283.43,953.33 398.33,953.33 v1(400,955)
PB4_SPI_MISO: J1.48 U1.162 | length 594.3
  Top Layer w10: v1(181.06,955) 325,955 340,940 380,940 390,930 573.19,930 585,918.19 U1.162@688.58,918.19
  Signal w10: v1@179.39,953.33 v1(181.06,955)
  Bottom Layer w10: J1.48@110.2,953.33 v1@179.39,953.33
PB5_SPI_MOSI: J1.49 U1.163 | length 414.8
  Top Layer w10: v1@630,898.5 U1.163@688.58,898.5
  Signal w10: v1(360,920) 440,920 461.5,898.5 v1@630,898.5
  Bottom Layer w10: J1.49@283.43,921.83 358.17,921.83 v1(360,920)
  other v1: 635,898.5
PB6_DCMI_D5: J1.50 U1.164 | length 601.9
  Top Layer w10: v1(181.06,920) 305.34,920 325.34,900 380,900 390,910 560,910 591.18,878.82 U1.164@688.58,878.82
  Bottom Layer w10: J1.50@112.03,920 v1(181.06,920)
PB7_DCMI_VS: J1.51 U1.165 | length 418.1
  Top Layer w10: v1(636.93,859.13) U1.165@688.58,859.13
  Signal w10: v1(399.66,890.34) 400,890 438.82,890 469.68,859.13 v1(636.93,859.13)
  Bottom Layer w10: J1.51@283.43,890.34 v1(399.66,890.34)
PB8_I2C1_SCL: J1.53 U1.167 | length 421.3
  Top Layer w10: v1(636.06,820) 636.3,819.76 U1.167@688.58,819.76
  Signal w10: v1(360,857.68) 437.32,857.68 475,820 v1(636.06,820)
  Bottom Layer w10: J1.53@283.43,858.84 358.84,858.84 v1(360,857.68)
PB9_I2C1_SDA: J1.54 U1.168 | length 616.1
  Top Layer w10: v1(181.06,860) 288.84,860 313.84,835 370,835 385,850 555.08,850 605,800.08 U1.168@688.58,800.08
  Signal w10: v1@179.9,858.84 v1(181.06,860)
  Bottom Layer w10: J1.54@110.2,858.84 v1@179.9,858.84
PB10_USART3_TX: J2.32 U1.79 | length 446.3
  Top Layer w10: U1.79@1676.77,1311.89 v1(1730,1311.89)
  Signal w10: v1(1730,1311.89) 1838.11,1311.89 1945,1205 v1(1970,1205)
  Bottom Layer w10: v1(1970,1205) 2059.7,1205 2060,1205.3 J2.32@2078.7,1205.3
PB11_USART3_RX: J2.31 U1.80 | length 644.3
  Top Layer w10: U1.80@1676.77,1331.57 1808.43,1331.57 1955,1185 1985,1185 1995,1195 2175,1195 v1(2185,1205)
  Bottom Layer w10: v1(2185,1205) 2185.3,1205.3 J2.31@2251.93,1205.3
PB12_CAN2_RX: J2.20 U1.92 | length 701.2
  Top Layer w10: U1.92@1546.85,1559.92 1546.85,1625.79 1556.06,1635 v1(1586.06,1635)
  Signal w10: v1(1586.06,1635) 1710,1635 1950,1395 v1(2010,1395)
  Bottom Layer w10: v1(2010,1395) 2010.73,1394.27 J2.20@2078.7,1394.27
PB13_CAN2_TX: J2.18 U1.93 | length 738.2
  Top Layer w10: U1.93@1527.17,1559.92 v1(1527.17,1613.9)
  Signal w10: v1(1527.17,1613.9) 1527.17,1641.1 1546.06,1660 1725,1660 1960,1425 v1(2010,1425)
  Bottom Layer w10: v1(2010,1425) 2010.77,1425.77 J2.18@2078.7,1425.77
PB14_OTG_HS_N: J2.21 U1.94 | length 998.7
  Top Layer w6: U1.94@1507.48,1559.92 1507.48,1600.83 1504.14,1604.17 1504.14,1630 1534.14,1660 1665,1660 2000,1325 2115,1325 2162,1372 2176.06,1372 v1(2181.06,1367) v1@2181.06,1372
  Bottom Layer w6: v1(2181.06,1367) 2193.45,1367 2197.68,1362.78 J2.21@2251.93,1362.78
PB15_OTG_HS_P: J2.19 U1.95 | length 1015.3
  Top Layer w6: U1.95@1487.8,1559.92 1487.8,1600.83 1491.14,1604.17 1491.14,1635.38 1528.75,1673 1670.38,1673 2005.38,1338 2109.62,1338 2156.62,1385 2176.06,1385 v1(2181.06,1390)
  Bottom Layer w6: v1(2181.06,1390) 2193.4,1390 2197.68,1394.27 J2.19@2251.93,1394.27
PC0_LED1: J2.72 U1.32 | length 865.4
  Top Layer w10: U1.32@1369.69,571.73 1369.69,515.31 v1(1370,515.63)
  Signal w10: v1(1370,515.63) 1460.63,425 1810,425 1960,575 v1(2010,575)
  Bottom Layer w10: v1(2010,575) 2010.38,575.38 J2.72@2078.7,575.38
PC1_ETH_MDC: J2.71 U1.33 | length 1019.6
  Top Layer w10: U1.33@1389.37,571.73 1389.37,506.69 1446.06,450 1850,450 1995,595 2140,595 2160,575 v1(2185,575)
  Bottom Layer w10: v1(2185,575) 2185.38,575.38 J2.71@2251.93,575.38
PC2_LED2: J2.70 U1.34 | length 823.2
  Top Layer w10: U1.34@1409.06,571.73 1409.06,515.94 1409.74,516.63 v1(1409.74,516.89) v1@1410,517.15
  Signal w10: v1(1409.74,516.89) 1481.63,445 1795,445 1955,605 v1(1970,605)
  Bottom Layer w10: v1(1970,605) 1971.87,606.87 J2.70@2078.7,606.87
PC3_LED3: J2.69 U1.35 | length 971.1
  Top Layer w10: U1.35@1428.74,571.73 1428.74,516.26 1475,470 1800,470 1955,625 1990,625 1995.63,619.37 2155.63,619.37 2170,605 v1(2185,605)
  Bottom Layer w10: v1(2185,605) 2186.87,606.87 J2.69@2251.93,606.87
PC4_RMII_RXD0: J2.53 U1.54 | length 604.7
  Top Layer w10: U1.54@1676.77,819.76 1900,819.76 1930.24,850 1985,850 2000,835 2036.16,835 2060,858.84 2183.84,858.84 v1(2185,860)
  Bottom Layer w10: v1(2185,860) 2186.16,858.84 J2.53@2251.93,858.84
PC5_RMII_RXD1: J2.52 U1.55 | length 423
  Top Layer w10: U1.55@1676.77,839.45 v1(1730.51,839.45)
  Signal w10: v1(1730.51,839.45) 1869.45,839.45 1920,890 v1(1970,890)
  Bottom Layer w10: v1(1970,890) 1970.34,890.34 J2.52@2078.7,890.34
PC6_DCMI_D0: J1.8 U1.115 | length 1313.1
  Top Layer w10: v1(175,1585) 175,1587 252,1664 530.06,1664 721.06,1855 959.38,1855 1094.09,1720.28 U1.115@1094.09,1559.92
  Bottom Layer w10: J1.8@110.2,1583.25 v1@175,1583.25
PC7_DCMI_D1: J1.9 U1.116 | length 1112.6
  Top Layer w10: v1(776.06,1835) 951.06,1835 1074.41,1711.65 U1.116@1074.41,1559.92
  Signal w10: v1(355,1550) 420,1550 570,1700 641.06,1700 v1(776.06,1835)
  Bottom Layer w10: J1.9@283.43,1551.75 353.25,1551.75 v1(355,1550)
PC8_SDIO_D0: J1.10 U1.117 | length 1235.6
  Top Layer w10: v1(184.57,1550) 205,1550 296,1641 552.06,1641 720.06,1809 942.06,1809 1054.72,1696.34 U1.117@1054.72,1559.92
  Signal w10: v1@182.82,1551.75 v1(184.57,1550)
  Bottom Layer w10: J1.10@110.2,1551.75 v1@182.82,1551.75
PC9_SDIO_D1: J1.11 U1.118 | length 1032.7
  Top Layer w10: v1(776.06,1790) 931.06,1790 1035.04,1686.02 U1.118@1035.04,1559.92
  Signal w10: v1@355,1520 430,1520 585.4,1675.4 661.46,1675.4 v1(776.06,1790)
  Bottom Layer w10: J1.11@283.43,1520.26 354.74,1520.26 v1@355,1520
  other v1: 355,1520.26
PC10_SDIO_D2: J1.29 U1.139 | length 460.7
  Top Layer w10: v1(637.01,1370.95) U1.139@688.58,1370.95
  Signal w10: v1(355,1236.79) 457.86,1236.79 592.01,1370.95 v1(637.01,1370.95)
  Bottom Layer w10: J1.29@283.43,1236.79 v1(355,1236.79)
PC11_SDIO_D3: J1.30 U1.140 | length 643.9
  Top Layer w10: v1(179.27,1236.79) 318.21,1236.79 340,1215 380,1215 401.79,1236.79 502.86,1236.79 617.32,1351.26 U1.140@688.58,1351.26
  Bottom Layer w10: J1.30@110.2,1236.79 v1(179.27,1236.79)
PC12_SDIO_CLK: J1.31 U1.141 | length 461.9
  Top Layer w10: v1(637.64,1331.57) U1.141@688.58,1331.57
  Signal w10: v1(395,1200) 466.06,1200 597.64,1331.57 v1(637.64,1331.57)
  Bottom Layer w10: J1.31@283.43,1205.3 283.72,1205 390,1205 v1(395,1200)
PC13: J1.70 U1.8 | length 1109.8
  Top Layer w10: v1(180,605) 255,605 320,540 320,445 420,345 781.06,345 897.24,461.18 U1.8@897.24,571.73
  Bottom Layer w10: J1.70@110.2,606.87 178.13,606.87 v1(180,605)
PC14: C8.1 R1.2 U1.9 X1.2 | length 373.2
  Top Layer w10: C8.1@895.51,230 868.27,257.24 X1.2@868.27,310 868.27,371.65 R1.2@891.61,395 916.93,420.32 U1.9@916.93,571.73
PC15: C9.1 R1.1 U1.10 X1.1 | length 368.2
  Top Layer w10: U1.10@936.61,571.73 936.61,418.9 R1.1@960.51,395 981.06,374.45 X1.1@981.06,310 981.06,249.45 C9.1@961.61,230
PD0_SMC_D2: J1.32 U1.142 | length 643.5
  Top Layer w10: v1(180,1205) 320,1205 330,1195 365,1195 380,1180 480,1180 611.89,1311.89 U1.142@688.58,1311.89
  Signal w10: v1@179.7,1205.3 v1(180,1205)
  Bottom Layer w10: J1.32@110.2,1205.3 v1@179.7,1205.3
PD1_SMC_D3: J1.33 U1.143 | length 454.2
  Top Layer w10: v1(635,1291.52) 635.69,1292.2 U1.143@688.58,1292.2
  Signal w10: v1(355,1173.8) 488.8,1173.8 606.52,1291.52 v1(635,1291.52)
  Bottom Layer w10: J1.33@283.43,1173.8 v1(355,1173.8)
PD2_SDIO_CMD: J1.34 U1.144 | length 639
  Top Layer w10: v1(182.26,1173.8) 316.2,1173.8 340,1150 370,1150 384,1164 520.06,1164 628.58,1272.52 U1.144@688.58,1272.52
  Bottom Layer w10: J1.34@110.2,1173.8 v1(182.26,1173.8)
PD3_CTP_SDA: J1.35 U1.145 | length 450.9
  Top Layer w10: v1(638.23,1252.83) U1.145@688.58,1252.83
  Signal w10: v1(395,1142.31) 527.7,1142.31 v1(638.23,1252.83)
  Bottom Layer w10: J1.35@283.43,1142.31 v1(395,1142.31)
